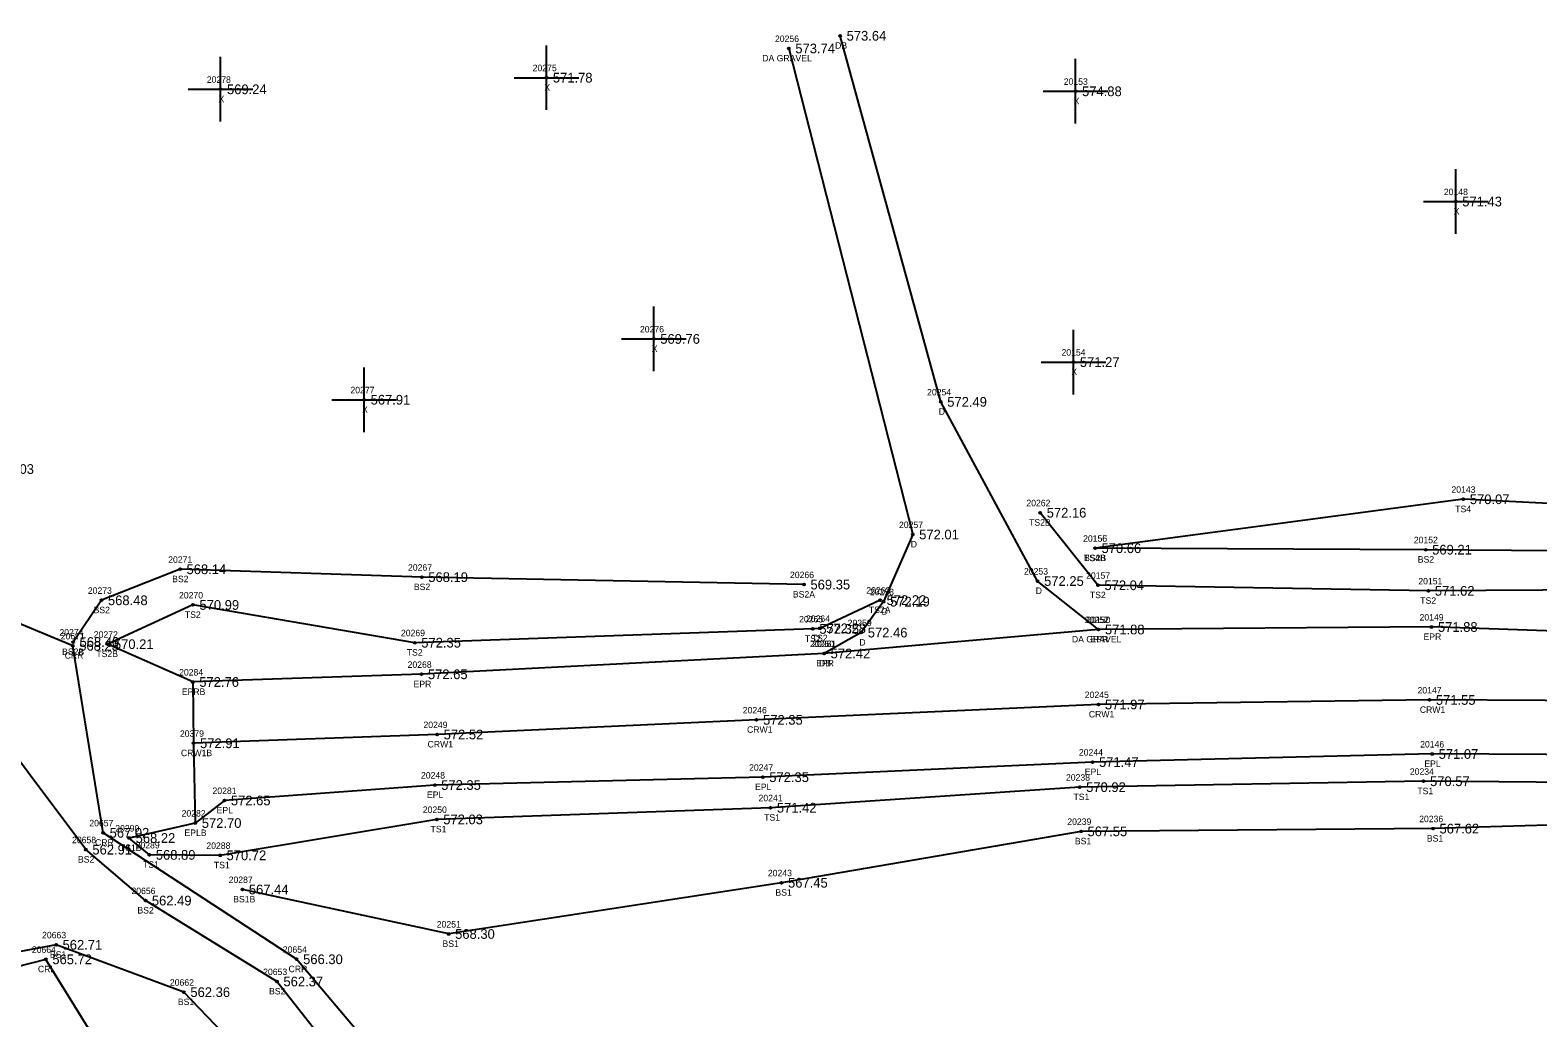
# Model space of a CAD drawing. Extents: x 1530159 to 1531652, y 877045 to 877724.
# Drawn here: x 1530915.9 to 1531149.1, y 877232.3 to 877385.1 of the extents above; entities that cross this region are included whole.
import ezdxf

# ---------------------------------------------------------------- set-up
doc = ezdxf.new("R2010")
doc.units = 0
for name, color, linetype in [('RD_DTM_BkLn1', 7, 'Continuous'), ('RD_DTM_BkLn2', 7, 'Continuous'), ('RD_DTM_BkLn_txCode', 7, 'Continuous'), ('RD_EX_Driveway', 7, 'Continuous'), ('RD_EX_Driveway_txCode', 7, 'Continuous'), ('RD_EX_H2O', 7, 'Continuous'), ('RD_EX_H2O_txCode', 7, 'Continuous'), ('RD_EX_Misc', 7, 'Continuous'), ('RD_EX_Misc_txCode', 7, 'Continuous'), ('RD_EX_Road', 7, 'Continuous'), ('RD_EX_Road_txCode', 7, 'Continuous'), ('RD_EX_TX_Driveway_ELEV', 7, 'Continuous'), ('RD_EX_TX_H2O_ELEV', 7, 'Continuous'), ('RD_EX_TX_Misc_ELEV', 7, 'Continuous'), ('RD_EX_TX_Road_ELEV', 7, 'Continuous'), ('RD_HC_Survey_ELEV', 7, 'Continuous'), ('RD_HC_Survey_txCode', 7, 'Continuous'), ('RD_SMD_Locator', 7, 'Continuous')]:
    doc.layers.add(name, color=color, linetype=linetype)

msp = doc.modelspace()

# ---------------------------------------------------------------- linework, layer by layer
at = {"layer": 'RD_DTM_BkLn1'}
msp.add_lwpolyline([(1531601.44, 877127.51), (1531558.79, 877158.11), (1531516.37, 877185.16), (1531470.77, 877211.58), (1531426.8, 877229.22), (1531379.86, 877245.66), (1531330.99, 877260.09), (1531284.24, 877270.97), (1531236.44, 877276.73), (1531185.96, 877281.19), (1531132.29, 877281.48), (1531081.11, 877280.78), (1531028.25, 877278.4), (1530978.85, 877276.13), (1530941.18, 877274.78)], dxfattribs=at)
at = {"layer": 'RD_DTM_BkLn2'}
msp.add_line((1530941.06, 877284.26), (1530927.86, 877290.11), dxfattribs=at)
for points in [[(1530978.51, 877193.14), (1530957.83, 877217.34), (1530939.69, 877236.27), (1530919.92, 877243.6), (1530901.7, 877240.19), (1530890.91, 877253.72), (1530883.61, 877289.66), (1530871.34, 877309.06), (1530854.23, 877336.62), (1530832.44, 877361.15), (1530819.05, 877374.38), (1530808.85, 877385.69), (1530794.67, 877405.25), (1530798.76, 877416.08), (1530761.4, 877471.05), (1530729.88, 877527.47), (1530702.64, 877561.57), (1530689.57, 877599.12), (1530672.36, 877642.36), (1530634.08, 877679.71), (1530613.02, 877709.76)], [(1531284.02, 877295.62), (1531283.07, 877300.66), (1531236.17, 877306.16), (1531185.36, 877310.1), (1531137.54, 877312.53), (1531080.59, 877304.96)], [(1531284.02, 877295.62), (1531278.88, 877288.92), (1531237.24, 877296.22), (1531185.24, 877298.68), (1531132.13, 877298.36), (1531081.04, 877299.23), (1531072.11, 877310.45)], [(1531280.81, 877296.56), (1531235.14, 877301.19), (1531184.71, 877304.32), (1531131.72, 877304.73), (1531080.59, 877304.96)], [(1531035.58, 877299.33), (1530976.48, 877300.48), (1530939.09, 877301.7), (1530926.94, 877296.9), (1530922.55, 877290.44)], [(1531047.35, 877296.93), (1531038.02, 877292.56), (1531036.96, 877292.47), (1530975.39, 877290.34), (1530941.09, 877296.18), (1530927.86, 877290.11)], [(1531348.08, 877109.37), (1531329.65, 877115.18), (1531326.16, 877131.65), (1531301.87, 877132.06), (1531267.22, 877105.63), (1531250.04, 877095.06), (1531235.2, 877094.62), (1531224.6, 877103.25), (1531205.62, 877122.91), (1531190.69, 877134.41), (1531175.3, 877135.54), (1531152.78, 877149.76), (1531124.21, 877153.63), (1531078.42, 877140.23), (1531063.23, 877144), (1531046.52, 877162.43), (1531018.22, 877188.5), (1530969.53, 877218.21), (1530954.08, 877237.92), (1530933.73, 877250.44), (1530924.53, 877258.32), (1530897.88, 877293.87)], [(1530941.06, 877284.26), (1530941.18, 877274.78), (1530941.45, 877262.44), (1530931.22, 877260.12)], [(1531360.93, 877233.21), (1531326.16, 877244.88), (1531283.1, 877256.15), (1531233.71, 877264.07), (1531183.7, 877268.46), (1531131.39, 877268.9), (1531078.21, 877267.99), (1531030.38, 877264.81), (1530978.79, 877263), (1530945.28, 877257.44), (1530934.34, 877257.51), (1530931.22, 877260.12)], [(1531359.18, 877233.58), (1531325.05, 877242.6), (1531281.34, 877252.7), (1531233.11, 877259.25), (1531182.65, 877263.04), (1531132.85, 877261.57), (1531078.42, 877261.15), (1531032.11, 877253.2), (1530980.63, 877245.27), (1530948.73, 877252.16)]]:
    msp.add_lwpolyline(points, dxfattribs=at)
at = {"layer": 'RD_EX_Driveway'}
for points in [[(1531081.11, 877292.38), (1531071.71, 877299.88), (1531056.73, 877327.6), (1531041.17, 877384.24)], [(1531033.24, 877382.28), (1531052.39, 877307.08), (1531047.89, 877296.69), (1531044.44, 877291.9), (1531038.69, 877288.67)]]:
    msp.add_lwpolyline(points, dxfattribs=at)
at = {"layer": 'RD_EX_H2O'}
for points in [[(1530972.1, 877196.48), (1530925.87, 877229.17), (1530918.34, 877241.35), (1530897.53, 877235.99), (1530881.25, 877248.19), (1530880.72, 877258.4), (1530879.1, 877290.18), (1530865.94, 877309.23), (1530832.49, 877347.64), (1530816.44, 877373.18)], [(1531348.73, 877112.8), (1531330.35, 877118.79), (1531327.02, 877134.75), (1531298.38, 877136.98), (1531263.7, 877109.21), (1531249.44, 877098.17), (1531237.97, 877099.69), (1531227.95, 877107.18), (1531213.47, 877126.62), (1531190.85, 877137.63), (1531178.72, 877139.79), (1531157.55, 877153.22), (1531117.73, 877159.68), (1531079.2, 877144.08), (1531065.91, 877145.46), (1531049.8, 877164.02), (1531030.35, 877191.82), (1530971.87, 877223.83), (1530957.12, 877241.36), (1530927.2, 877260.93), (1530922.5, 877289.86), (1530895.04, 877301.24)]]:
    msp.add_lwpolyline(points, dxfattribs=at)
at = {"layer": 'RD_EX_Misc'}
for p, q in [((1530995.74, 877372.76), (1530995.74, 877382.76)), ((1530945.35, 877370.96), (1530945.35, 877380.96)), ((1531077.58, 877370.65), (1531077.58, 877380.65)), ((1530990.74, 877377.76), (1531000.74, 877377.76)), ((1530940.35, 877375.96), (1530950.35, 877375.96)), ((1531072.58, 877375.65), (1531082.58, 877375.65)), ((1531136.37, 877353.59), (1531136.37, 877363.59)), ((1531131.37, 877358.59), (1531141.37, 877358.59)), ((1531012.35, 877332.34), (1531012.35, 877342.34)), ((1531007.35, 877337.34), (1531017.35, 877337.34)), ((1531077.24, 877328.76), (1531077.24, 877338.76)), ((1530967.56, 877322.93), (1530967.56, 877332.93)), ((1531072.24, 877333.76), (1531082.24, 877333.76)), ((1530962.56, 877327.93), (1530972.56, 877327.93))]:
    msp.add_line(p, q, dxfattribs=at)
at = {"layer": 'RD_EX_Road'}
for points in [[(1531606.64, 877133.84), (1531579.15, 877155.05), (1531564.87, 877165.27), (1531535.22, 877186.03), (1531511.53, 877200.27), (1531474.57, 877218.9), (1531430.45, 877239.35), (1531404.48, 877249.38), (1531382.32, 877256.43), (1531333.23, 877270.71), (1531303.67, 877277.44), (1531276.52, 877282.71), (1531237.32, 877287.2), (1531185.8, 877290.94), (1531132.61, 877292.77), (1531081.11, 877292.38), (1531038.69, 877288.67), (1530976.42, 877285.45), (1530941.06, 877284.26)], [(1531595.27, 877120.27), (1531553.56, 877149.9), (1531509.97, 877177.57), (1531465.94, 877201.73), (1531423.65, 877222), (1531376.09, 877237.68), (1531328.84, 877252.31), (1531282.81, 877261.85), (1531235.7, 877268.49), (1531185.47, 877272.84), (1531132.72, 877273.12), (1531080.2, 877271.87), (1531029.21, 877269.53), (1530978.47, 877268.32), (1530945.95, 877265.93), (1530941.45, 877262.44)]]:
    msp.add_lwpolyline(points, dxfattribs=at)
at = {"layer": 'RD_SMD_Locator'}
for centre in [(1531041.17, 877384.24), (1531033.24, 877382.28), (1530995.74, 877377.76), (1530945.35, 877375.96), (1531077.58, 877375.65), (1531136.37, 877358.59), (1531012.35, 877337.34), (1531077.24, 877333.76), (1530967.56, 877327.93), (1531056.73, 877327.6), (1531137.54, 877312.53), (1531072.11, 877310.45), (1531052.39, 877307.08), (1531080.59, 877304.96), (1531080.59, 877304.96), (1531131.72, 877304.73), (1530939.09, 877301.7), (1530976.48, 877300.48), (1531071.71, 877299.88), (1531035.58, 877299.33), (1531081.04, 877299.23), (1531132.13, 877298.36), (1530926.94, 877296.9), (1530941.09, 877296.18), (1531047.35, 877296.93), (1531047.89, 877296.69), (1531036.96, 877292.47), (1531038.02, 877292.56), (1531044.44, 877291.9), (1531081.11, 877292.38), (1531081.11, 877292.38), (1531132.61, 877292.77), (1530922.5, 877289.86), (1530922.55, 877290.44), (1530927.86, 877290.11), (1530975.39, 877290.34), (1531038.69, 877288.67), (1531038.69, 877288.67), (1530941.06, 877284.26), (1530976.42, 877285.45), (1531132.29, 877281.48), (1531081.11, 877280.78), (1531028.25, 877278.4), (1530941.18, 877274.78), (1530978.85, 877276.13), (1531080.2, 877271.87), (1531132.72, 877273.12), (1531029.21, 877269.53), (1530978.47, 877268.32), (1531078.21, 877267.99), (1531131.39, 877268.9), (1530945.95, 877265.93), (1530978.79, 877263), (1531030.38, 877264.81), (1530927.2, 877260.93), (1530941.45, 877262.44), (1531078.42, 877261.15), (1531132.85, 877261.57), (1530924.53, 877258.32), (1530931.22, 877260.12), (1530934.34, 877257.51), (1530945.28, 877257.44), (1531032.11, 877253.2), (1530948.73, 877252.16), (1530933.73, 877250.44), (1530980.63, 877245.27), (1530919.92, 877243.6), (1530918.34, 877241.35), (1530957.12, 877241.36), (1530954.08, 877237.92), (1530939.69, 877236.27)]:
    msp.add_circle(centre, 0.15, dxfattribs=at)

# ---------------------------------------------------------------- texts
at = {"layer": 'RD_DTM_BkLn_txCode'}
for s, p in [('20143', (1531135.7, 877313.53)), ('20262', (1531069.97, 877311.45)), ('TS2B', (1531070.39, 877308.45)), ('TS4', (1531136.29, 877310.53)), ('20156', (1531078.73, 877305.96)), ('20155', (1531078.75, 877305.96)), ('20152', (1531129.88, 877305.73)), ('20271', (1530937.26, 877302.7)), ('20267', (1530974.34, 877301.48)), ('TS4B', (1531078.87, 877302.96)), ('BS2B', (1531078.89, 877302.96)), ('BS2', (1531130.49, 877302.73)), ('BS2', (1530937.87, 877299.7)), ('20266', (1531033.41, 877300.33)), ('20157', (1531079.2, 877300.23)), ('20151', (1531130.58, 877299.36)), ('20273', (1530924.83, 877297.9)), ('20270', (1530938.93, 877297.18)), ('BS2', (1530975.25, 877298.48)), ('BS2A', (1531033.86, 877297.33)), ('20263', (1531045.21, 877297.93)), ('TS2', (1531079.79, 877297.23)), ('BS2', (1530925.72, 877294.9)), ('TS2A', (1531045.61, 877294.93)), ('TS2', (1531130.88, 877296.36)), ('TS2', (1530939.84, 877294.18)), ('20265', (1531034.82, 877293.47)), ('20264', (1531035.88, 877293.56)), ('20274', (1530920.43, 877291.44)), ('20272', (1530925.75, 877291.11)), ('20269', (1530973.25, 877291.34)), ('TS2', (1531035.72, 877290.47)), ('TS2', (1531036.78, 877290.56)), ('BS2B', (1530920.85, 877288.44)), ('TS2B', (1530926.15, 877288.11)), ('TS2', (1530974.15, 877288.34)), ('20238', (1531076.09, 877268.99)), ('20234', (1531129.27, 877269.9)), ('TS1', (1531130.43, 877266.9)), ('20250', (1530976.63, 877264)), ('20241', (1531028.55, 877265.81)), ('TS1', (1531077.25, 877265.99)), ('TS1', (1531029.42, 877262.81)), ('20239', (1531076.3, 877262.15)), ('20236', (1531130.71, 877262.57)), ('20658', (1530922.39, 877259.32)), ('20290', (1530929.07, 877261.12)), ('TS1', (1530977.83, 877261)), ('BS1', (1531131.9, 877259.57)), ('TS1B', (1530929.79, 877258.12)), ('20289', (1530932.22, 877258.51)), ('20288', (1530943.16, 877258.44)), ('BS1', (1531077.47, 877259.15)), ('BS2', (1530923.3, 877256.32)), ('TS1', (1530933.37, 877255.51)), ('TS1', (1530944.32, 877255.44)), ('20287', (1530946.61, 877253.16)), ('20243', (1531029.99, 877254.2)), ('20656', (1530931.57, 877251.44)), ('BS1B', (1530947.31, 877250.16)), ('BS1', (1531031.16, 877251.2)), ('BS2', (1530932.5, 877248.44)), ('20251', (1530978.79, 877246.27)), ('20663', (1530917.75, 877244.6)), ('BS1', (1530979.68, 877243.27)), ('BS1', (1530918.97, 877241.6)), ('20653', (1530951.94, 877238.92)), ('20662', (1530937.52, 877237.27)), ('BS1', (1530938.75, 877234.27)), ('BS2', (1530952.85, 877235.92))]:
    msp.add_text(s, height=1, dxfattribs=at).set_placement(p)
at = {"layer": 'RD_EX_Driveway_txCode'}
for s, p in [('20256', (1531031.09, 877383.28)), ('DB', (1531040.39, 877382.24)), ('DA GRAVEL', (1531029.13, 877380.28)), ('20254', (1531054.61, 877328.6)), ('D', (1531056.42, 877325.6)), ('20257', (1531050.27, 877308.08)), ('D', (1531052.09, 877305.08)), ('20253', (1531069.6, 877300.88)), ('20258', (1531045.77, 877297.69)), ('D', (1531071.41, 877297.88)), ('D', (1531047.58, 877294.69)), ('20259', (1531042.33, 877292.9)), ('20252', (1531079, 877293.38)), ('20260', (1531036.51, 877289.67)), ('D', (1531044.14, 877289.9)), ('DA GRAVEL', (1531077.01, 877290.38)), ('DB', (1531037.91, 877286.67))]:
    msp.add_text(s, height=1, dxfattribs=at).set_placement(p)
at = {"layer": 'RD_EX_H2O_txCode'}
for s, p in [('20671', (1530920.64, 877290.86)), ('CRR', (1530921.25, 877287.86)), ('20657', (1530925.06, 877261.93)), ('CRR', (1530925.95, 877258.93)), ('20664', (1530916.17, 877242.35)), ('20654', (1530954.98, 877242.36)), ('CRL', (1530917.11, 877239.35)), ('CRR', (1530955.87, 877239.36))]:
    msp.add_text(s, height=1, dxfattribs=at).set_placement(p)
at = {"layer": 'RD_EX_Misc_txCode'}
for s, p in [('20275', (1530993.62, 877378.76)), ('20278', (1530943.23, 877376.96)), ('20153', (1531075.75, 877376.65)), ('X', (1530945.03, 877373.96)), ('X', (1530995.43, 877375.76)), ('X', (1531077.27, 877373.65)), ('20148', (1531134.53, 877359.59)), ('X', (1531136.05, 877356.59)), ('20276', (1531010.21, 877338.34)), ('X', (1531012.04, 877335.34)), ('20154', (1531075.4, 877334.76)), ('X', (1531076.92, 877331.76)), ('20277', (1530965.44, 877328.93)), ('X', (1530967.24, 877325.93))]:
    msp.add_text(s, height=1, dxfattribs=at).set_placement(p)
at = {"layer": 'RD_EX_Road_txCode'}
for s, p in [('20150', (1531079.24, 877293.38)), ('20149', (1531130.77, 877293.77)), ('20261', (1531036.83, 877289.67)), ('EPR', (1531079.89, 877290.38)), ('EPR', (1531131.38, 877290.77)), ('20284', (1530938.94, 877285.26)), ('20268', (1530974.28, 877286.45)), ('EPR', (1531037.46, 877286.67)), ('EPR', (1530975.2, 877283.45)), ('EPRB', (1530939.36, 877282.26)), ('20146', (1531130.86, 877274.12)), ('20244', (1531078.09, 877272.87)), ('EPL', (1531131.51, 877271.12)), ('20248', (1530976.35, 877269.32)), ('20247', (1531027.09, 877270.53)), ('EPL', (1531079, 877269.87)), ('20281', (1530944.11, 877266.93)), ('EPL', (1530977.27, 877266.32)), ('EPL', (1531028.01, 877267.53)), ('20282', (1530939.33, 877263.44)), ('EPL', (1530944.74, 877263.93)), ('EPLB', (1530939.77, 877260.44))]:
    msp.add_text(s, height=1, dxfattribs=at).set_placement(p)
at = {"layer": 'RD_EX_TX_Driveway_ELEV'}
for s, p in [('573.64', (1531042.17, 877383.49)), ('573.74', (1531034.24, 877381.53)), ('572.49', (1531057.73, 877326.85)), ('572.01', (1531053.39, 877306.33)), ('572.25', (1531072.71, 877299.13)), ('572.19', (1531048.89, 877295.94)), ('571.88', (1531082.11, 877291.63)), ('572.46', (1531045.44, 877291.15)), ('572.42', (1531039.69, 877287.92))]:
    msp.add_text(s, height=1.5, dxfattribs=at).set_placement(p)
at = {"layer": 'RD_EX_TX_H2O_ELEV'}
for s, p in [('568.23', (1530923.5, 877289.11)), ('567.02', (1530928.2, 877260.18)), ('565.72', (1530919.34, 877240.6)), ('566.30', (1530958.12, 877240.61))]:
    msp.add_text(s, height=1.5, dxfattribs=at).set_placement(p)
at = {"layer": 'RD_EX_TX_Misc_ELEV'}
for s, p in [('571.78', (1530996.74, 877377.01)), ('569.24', (1530946.35, 877375.21)), ('574.88', (1531078.58, 877374.9)), ('571.43', (1531137.37, 877357.84)), ('569.76', (1531013.35, 877336.59)), ('571.27', (1531078.24, 877333.01)), ('567.91', (1530968.56, 877327.18)), ('568.03', (1530910.36, 877316.46)), ('570.07', (1531138.54, 877311.78)), ('572.16', (1531073.11, 877309.7)), ('570.66', (1531081.59, 877304.21)), ('570.66', (1531081.59, 877304.21)), ('569.21', (1531132.72, 877303.98)), ('568.14', (1530940.09, 877300.95)), ('568.19', (1530977.48, 877299.73)), ('569.35', (1531036.58, 877298.58)), ('572.04', (1531082.04, 877298.48)), ('568.48', (1530927.94, 877296.15)), ('572.22', (1531048.35, 877296.18)), ('571.62', (1531133.13, 877297.61)), ('570.99', (1530942.09, 877295.43)), ('572.35', (1531037.96, 877291.72)), ('572.28', (1531039.02, 877291.81)), ('568.40', (1530923.55, 877289.69)), ('570.21', (1530928.86, 877289.36)), ('572.35', (1530976.39, 877289.59)), ('570.57', (1531132.39, 877268.15)), ('570.92', (1531079.21, 877267.24)), ('571.42', (1531031.38, 877264.06)), ('572.03', (1530979.79, 877262.25)), ('568.22', (1530932.22, 877259.37)), ('567.55', (1531079.42, 877260.4)), ('567.62', (1531133.85, 877260.82)), ('562.91', (1530925.53, 877257.57)), ('568.89', (1530935.34, 877256.76)), ('570.72', (1530946.28, 877256.69)), ('567.45', (1531033.11, 877252.45)), ('562.49', (1530934.73, 877249.69)), ('567.44', (1530949.73, 877251.41)), ('562.71', (1530920.92, 877242.85)), ('568.30', (1530981.63, 877244.52)), ('562.36', (1530940.69, 877235.52)), ('562.37', (1530955.08, 877237.17))]:
    msp.add_text(s, height=1.5, dxfattribs=at).set_placement(p)
at = {"layer": 'RD_EX_TX_Road_ELEV'}
for s, p in [('571.88', (1531082.11, 877291.63)), ('571.88', (1531133.61, 877292.02)), ('572.42', (1531039.69, 877287.92)), ('572.65', (1530977.42, 877284.7)), ('572.76', (1530942.06, 877283.51)), ('571.47', (1531081.2, 877271.12)), ('571.07', (1531133.72, 877272.37)), ('572.35', (1531030.21, 877268.78)), ('572.35', (1530979.47, 877267.57)), ('572.65', (1530946.95, 877265.18)), ('572.70', (1530942.45, 877261.69))]:
    msp.add_text(s, height=1.5, dxfattribs=at).set_placement(p)
at = {"layer": 'RD_HC_Survey_ELEV'}
for s, p in [('571.97', (1531082.11, 877280.03)), ('571.55', (1531133.29, 877280.73)), ('572.35', (1531029.25, 877277.65)), ('572.52', (1530979.85, 877275.38)), ('572.91', (1530942.18, 877274.03))]:
    msp.add_text(s, height=1.5, dxfattribs=at).set_placement(p)
at = {"layer": 'RD_HC_Survey_txCode'}
for s, p in [('20245', (1531079, 877281.78)), ('20147', (1531130.46, 877282.48)), ('20246', (1531026.11, 877279.4)), ('CRW1', (1531079.63, 877278.78)), ('CRW1', (1531130.81, 877279.48)), ('20379', (1530939.07, 877275.78)), ('20249', (1530976.73, 877277.13)), ('CRW1', (1531026.77, 877276.4)), ('CRW1', (1530977.37, 877274.13)), ('CRW1B', (1530939.23, 877272.78))]:
    msp.add_text(s, height=1, dxfattribs=at).set_placement(p)

doc.saveas('drawing.dxf')
